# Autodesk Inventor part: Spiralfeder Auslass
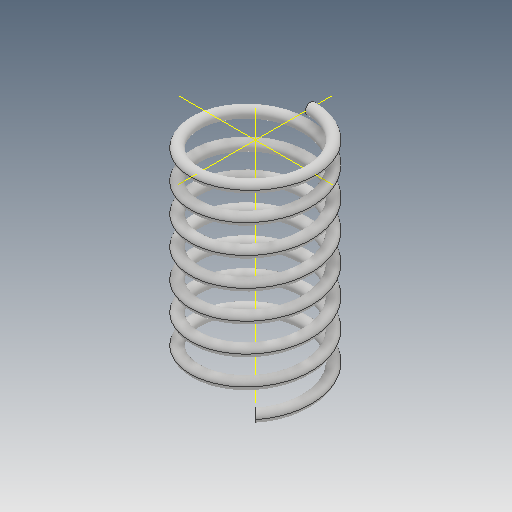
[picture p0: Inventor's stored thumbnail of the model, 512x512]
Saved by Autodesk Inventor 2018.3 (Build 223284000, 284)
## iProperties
Created: 2019-01
Part Number: Spiralfeder Auslass
Material: Generisch
Document SubType Name: Modeling
Designer: tobiassandmann
Density: 1 g/cm^3
Appearance: Vorgabe
Mass: 0.0793279 g
Surface Area: 4.24641 cm^2
Volume: 0.0793279 cm^3
Author: tobiassandmann
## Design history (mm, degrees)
sketch "Skizze1"
  geometry: L1 (0, 0)-(3.5, 0); L2 (3.5, 0)-(3.875, 0); L3 (0, 0)-(0, -14); C1 r 0.375 at (3.875, 0)
  constraints: 6 end point, 2 horizontal, 1 centre point, 1 coincident, 1 vertical
  dimensions: "d0" = 3.5 distance of L1.start L1.end; "d1" = 0.375 distance of L1.end L2.end; "d2" = 0.75 diameter of C1; "d3" = 14 distance of L1.start L3.end
feature "Spirale1" sketch "Skizze1" pitch "d4" = 2; turns "d6" = 14; dims "d5" = 14, "d7" = 0, angle "d8" = 90 deg, angle "d9" = 90 deg, "d10" = 0, "d11" = 0
node "Volumenkörper1"
